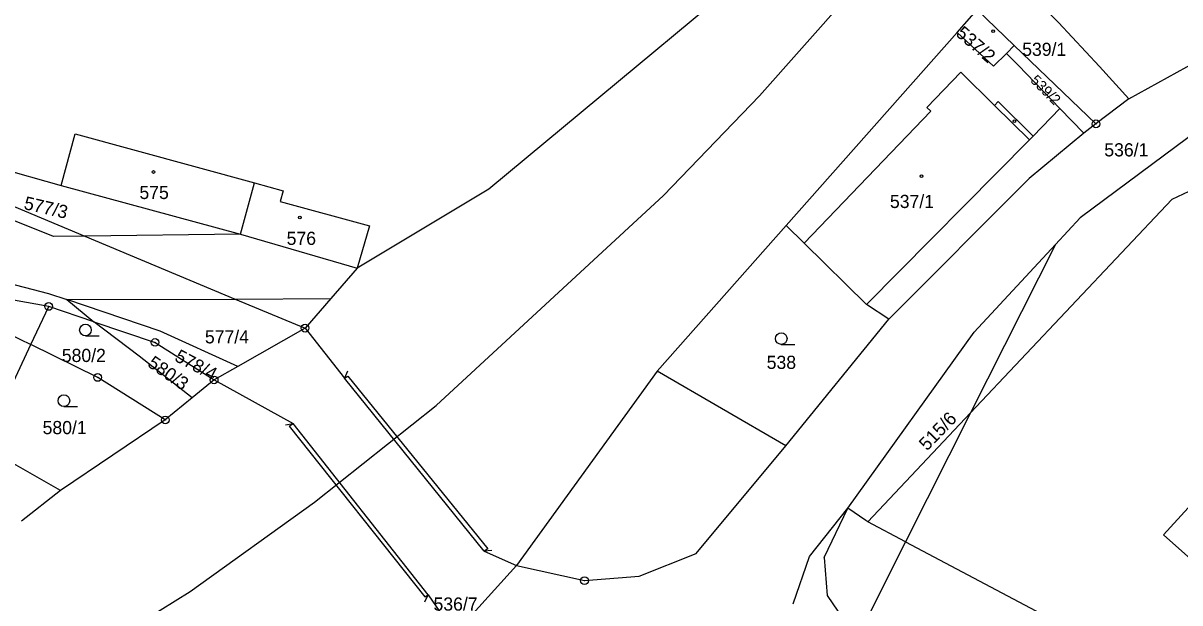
# Model space of a CAD drawing. Extents: x -776701 to -776081, y -974398 to -973771.
# Drawn here: x -776380.3 to -776231, y -974262.5 to -974187.7 of the extents above; entities that cross this region are included whole.
import ezdxf

# ---------------------------------------------------------------- set-up
doc = ezdxf.new("R2010")
doc.units = 0
for name, color, linetype in [('Hranice parcel', 7, 'Continuous'), ('Parcelní čísla', 7, 'Continuous'), ('Poz předměty', 7, 'Continuous'), ('Vnitřní kresba', 7, 'Continuous'), ('Značky bodu BP', 7, 'Continuous'), ('Značky budov', 7, 'Continuous'), ('Značky kultur', 7, 'Continuous')]:
    doc.layers.add(name, color=color, linetype=linetype)

msp = doc.modelspace()

# ---------------------------------------------------------------- linework, layer by layer
at = {"layer": 'Hranice parcel'}
for p, q in [((-776257.21, -974185.99), (-776252.4, -974190.58)), ((-776281.83, -974213.8), (-776259.77, -974188.9)), ((-776252.4, -974190.58), (-776253.41, -974191.59)), ((-776252.4, -974190.58), (-776241.86, -974200.69)), ((-776237.63, -974197.45), (-776241.86, -974200.69)), ((-776414.02, -974197.79), (-776375.42, -974208.63)), ((-776241.86, -974200.69), (-776243.42, -974201.88)), ((-776375.42, -974208.63), (-776352.27, -974214.94)), ((-776352.27, -974214.94), (-776350.46, -974208.3)), ((-776352.27, -974214.94), (-776372.39, -974215.17)), ((-776352.27, -974214.94), (-776337.22, -974219.32)), ((-776337.22, -974219.32), (-776340.63, -974223.24)), ((-776379.34, -974229.15), (-776377.04, -974224.25)), ((-776371.21, -974226.22), (-776377.04, -974224.25)), ((-776374.7, -974223.37), (-776371.21, -974226.22)), ((-776281.91, -974242.23), (-776268.6, -974225.89)), ((-776370.72, -974233.41), (-776379.34, -974229.15)), ((-776352.62, -974231.99), (-776355.69, -974233.73)), ((-776361.99, -974238.89), (-776370.72, -974233.41)), ((-776355.69, -974233.73), (-776358.51, -974236.04)), ((-776358.51, -974236.04), (-776361.99, -974238.89)), ((-776361.99, -974238.89), (-776375.51, -974247.99)), ((-776375.51, -974247.99), (-776380.54, -974251.96)), ((-776266.43, -974254.64), (-776223.5, -974277.28))]:
    msp.add_line(p, q, dxfattribs=at)
for points in [[(-776274.82, -974171.4), (-776320.22, -974209.13), (-776324.76, -974211.83), (-776337.22, -974219.32)], [(-776253.13, -974181.24), (-776249.5, -974184.85), (-776246.7, -974187.6), (-776241.4, -974193.3), (-776237.63, -974197.45)], [(-776259.77, -974188.9), (-776257.88, -974186.77), (-776257.21, -974185.99)], [(-776237.63, -974197.45), (-776226.37, -974191.27), (-776214.42, -974187)], [(-776253.41, -974191.59), (-776255.08, -974193.24), (-776259.77, -974188.9)], [(-776253.41, -974191.59), (-776251.85, -974193.15), (-776246.5, -974198.7), (-776243.42, -974201.88)], [(-776219.11, -974197.62), (-776228.51, -974201.38), (-776243.91, -974212.83), (-776247.1, -974216.26)], [(-776243.42, -974201.88), (-776250.49, -974207.74), (-776268.6, -974225.89)], [(-776375.42, -974208.63), (-776373.61, -974201.99), (-776350.46, -974208.3)], [(-776372.39, -974215.17), (-776376.43, -974215.22), (-776405.4, -974203.66)], [(-776350.46, -974208.3), (-776346.77, -974209.31), (-776347.15, -974210.71), (-776335.64, -974213.84), (-776337.22, -974219.32)], [(-776281.91, -974242.23), (-776298.48, -974232.58), (-776281.83, -974213.8)], [(-776268.6, -974225.89), (-776271.48, -974223.98), (-776279.53, -974216.07), (-776281.83, -974213.8)], [(-776273.87, -974250.3), (-776257.6, -974227.55), (-776247.1, -974216.26)], [(-776247.1, -974216.26), (-776258.04, -974237.98), (-776266.43, -974254.64)], [(-776396.96, -974217.4), (-776377.08, -974222.57), (-776374.7, -974223.37)], [(-776377.04, -974224.25), (-776384.52, -974222.93), (-776389.85, -974221.65), (-776397.85, -974219.54)], [(-776374.7, -974223.37), (-776352.96, -974223.29), (-776340.63, -974223.24)], [(-776352.62, -974231.99), (-776362.64, -974227.45), (-776374.7, -974223.37)], [(-776340.63, -974223.24), (-776343.95, -974227.05), (-776352.62, -974231.99)], [(-776371.21, -974226.22), (-776363.31, -974228.89), (-776355.69, -974233.73)], [(-776358.51, -974236.04), (-776365.36, -974230.68), (-776371.21, -974226.22)], [(-776375.51, -974247.99), (-776385.52, -974242.34), (-776379.34, -974229.15)], [(-776322.34, -974263.94), (-776316.64, -974257.67), (-776307.88, -974259.63), (-776300.82, -974259.07), (-776293.46, -974256.12), (-776281.91, -974242.23)], [(-776280.95, -974262.62), (-776278.84, -974256.52), (-776273.87, -974250.3)], [(-776266.43, -974254.64), (-776271.32, -974252.06), (-776271.57, -974251.89), (-776273.87, -974250.3)], [(-776266.43, -974254.64), (-776272.39, -974266.46), (-776279.48, -974280.55)]]:
    msp.add_lwpolyline(points, dxfattribs=at)
at = {"layer": 'Poz předměty'}
for p, q in [((-776285.27, -974197.08), (-776273.24, -974183.49)), ((-776297.69, -974209.94), (-776285.27, -974197.08)), ((-776327.03, -974237.01), (-776297.69, -974209.94)), ((-776342.73, -974249.52), (-776327.03, -974237.01)), ((-776358.8, -974261.05), (-776342.73, -974249.52)), ((-776375.83, -974271.58), (-776358.8, -974261.05))]:
    msp.add_line(p, q, dxfattribs=at)
at = {"layer": 'Vnitřní kresba'}
for p, q in [((-776189.94, -974190.42), (-776232.08, -974210.46)), ((-776263.67, -974198.56), (-776259.28, -974194)), ((-776259.28, -974194), (-776254.94, -974198.3)), ((-776414.02, -974197.79), (-776372.39, -974215.17)), ((-776263.16, -974199.04), (-776263.67, -974198.56)), ((-776254.94, -974198.3), (-776254.46, -974197.81)), ((-776254.94, -974198.3), (-776250.43, -974202.76)), ((-776254.46, -974197.81), (-776249.95, -974202.28)), ((-776249.95, -974202.28), (-776246.5, -974198.7)), ((-776263.16, -974199.04), (-776279.53, -974216.07)), ((-776250.43, -974202.76), (-776271.48, -974223.98)), ((-776249.95, -974202.28), (-776250.43, -974202.76)), ((-776258.04, -974237.98), (-776232.08, -974210.46)), ((-776372.39, -974215.17), (-776352.96, -974223.29)), ((-776233.13, -974253.7), (-776202.03, -974219.5)), ((-776352.96, -974223.29), (-776343.95, -974227.05)), ((-776343.95, -974227.05), (-776338.87, -974233.52)), ((-776382.19, -974227.77), (-776379.34, -974229.15)), ((-776338.46, -974232.61), (-776338.87, -974233.52)), ((-776338.87, -974233.52), (-776338.44, -974233.24)), ((-776338.44, -974233.24), (-776320.37, -974255.54)), ((-776298.48, -974232.58), (-776316.64, -974257.67)), ((-776355.69, -974233.73), (-776345.5, -974239.35)), ((-776320.82, -974255.81), (-776338.87, -974233.52)), ((-776271.32, -974252.06), (-776258.04, -974237.98)), ((-776346.48, -974239.54), (-776345.5, -974239.35)), ((-776346, -974239.7), (-776345.5, -974239.35)), ((-776346, -974239.7), (-776328.51, -974261.74)), ((-776328.07, -974261.46), (-776345.5, -974239.35)), ((-776276.96, -974256.63), (-776273.87, -974250.3)), ((-776164.96, -974314.87), (-776233.13, -974253.7)), ((-776320.37, -974255.54), (-776320.82, -974255.81)), ((-776319.82, -974255.72), (-776320.82, -974255.81)), ((-776320.82, -974255.81), (-776316.64, -974257.67)), ((-776276.96, -974256.63), (-776276.57, -974261.56)), ((-776328.51, -974261.74), (-776328.07, -974261.46)), ((-776328.48, -974262.37), (-776328.07, -974261.46)), ((-776328.07, -974261.46), (-776324.63, -974266.46)), ((-776276.57, -974261.56), (-776273.88, -974265.46))]:
    msp.add_line(p, q, dxfattribs=at)
at = {"layer": 'Značky bodu BP'}
for centre, radius in [((-776241.86, -974200.69), 0.5), ((-776241.86, -974200.69), 0.0303), ((-776377.04, -974224.25), 0.5), ((-776377.04, -974224.25), 0.0303), ((-776343.95, -974227.05), 0.5), ((-776343.95, -974227.05), 0.0303), ((-776363.31, -974228.89), 0.5), ((-776363.31, -974228.89), 0.0303), ((-776370.72, -974233.41), 0.5), ((-776355.69, -974233.73), 0.5), ((-776370.72, -974233.41), 0.0303), ((-776355.69, -974233.73), 0.0303), ((-776361.99, -974238.89), 0.5), ((-776361.99, -974238.89), 0.0303), ((-776307.88, -974259.63), 0.5), ((-776307.88, -974259.63), 0.0303)]:
    msp.add_circle(centre, radius, dxfattribs=at)
at = {"layer": 'Značky budov'}
for centre in [(-776255.12, -974188.74), (-776252.39, -974200.35), (-776363.51, -974206.9), (-776264.37, -974207.44), (-776344.61, -974212.78)]:
    msp.add_circle(centre, 0.175, dxfattribs=at)
at = {"layer": 'Značky kultur'}
for p, q in [((-776372.3, -974228.04), (-776370.55, -974228.04)), ((-776282.48, -974229.15), (-776280.73, -974229.15)), ((-776375.08, -974237.16), (-776373.33, -974237.16))]:
    msp.add_line(p, q, dxfattribs=at)
for centre in [(-776372.3, -974227.29), (-776282.48, -974228.4), (-776375.08, -974236.41)]:
    msp.add_circle(centre, 0.75, dxfattribs=at)

# ---------------------------------------------------------------- texts
at = {"layer": 'Parcelní čísla'}
for s, height, rotation, p in [('537/2', 1.7, 319, (-776260.06, -974189.21)), ('539/2', 1.347, 315, (-776250.41, -974195.18)), ('577/3', 1.7, 347, (-776380.35, -974211.67)), ('578/4', 1.7, 332, (-776360.91, -974231.2)), ('580/3', 1.7, 325, (-776364.41, -974231.89)), ('515/6', 1.7, 46, (-776263.66, -974242.96))]:
    msp.add_text(s, height=height, rotation=rotation, dxfattribs=at).set_placement(p)
for s, p in [('539/1', (-776251.38, -974191.92)), ('536/1', (-776240.78, -974204.89)), ('575', (-776365.33, -974210.39)), ('537/1', (-776268.45, -974211.55)), ('576', (-776346.33, -974216.31)), ('577/4', (-776356.88, -974229.02)), ('580/2', (-776375.35, -974231.42)), ('538', (-776284.36, -974232.31)), ('580/1', (-776377.83, -974240.73)), ('536/7', (-776327.37, -974263.5))]:
    msp.add_text(s, height=1.7, dxfattribs=at).set_placement(p)

doc.saveas('drawing.dxf')
